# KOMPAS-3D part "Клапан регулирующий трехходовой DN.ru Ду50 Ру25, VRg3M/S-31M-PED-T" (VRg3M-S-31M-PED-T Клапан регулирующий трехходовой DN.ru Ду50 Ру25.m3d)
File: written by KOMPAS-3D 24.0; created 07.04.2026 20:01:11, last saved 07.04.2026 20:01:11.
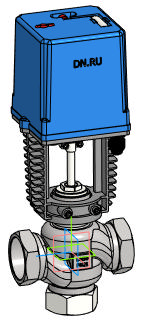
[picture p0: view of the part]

Document properties: Автор: DN.RU; Полное имя файла: D:\PROJECT CAD\DN.RU\...197(ACTUALE). VRg3M-S-31M-PED-T Клапан регулирующий трехходовой DN.ru\Исходники\DN50\VRg3M-S-31M-PED-T Клапан регулирующий трехходовой DN.ru Ду50 Ру25.m3d

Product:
- Body: Твердое тело1  | qty 1
    Масса: 22.748903
- Part/product: Клапан регулирующий трехходовой DN.ru Ду50 Ру25  | designation VRg3M/S-31M-PED-T
    Масса: 4.6
    Раздел спецификации: Прочие изделия
    Комментарий: D230-11268
    Примечание: D230-11268
    additional columns: Типовые

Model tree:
1. Твердое тело1  (labels: Твердое тело1)

Expressions: VRg3M/S-31M-PED-T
